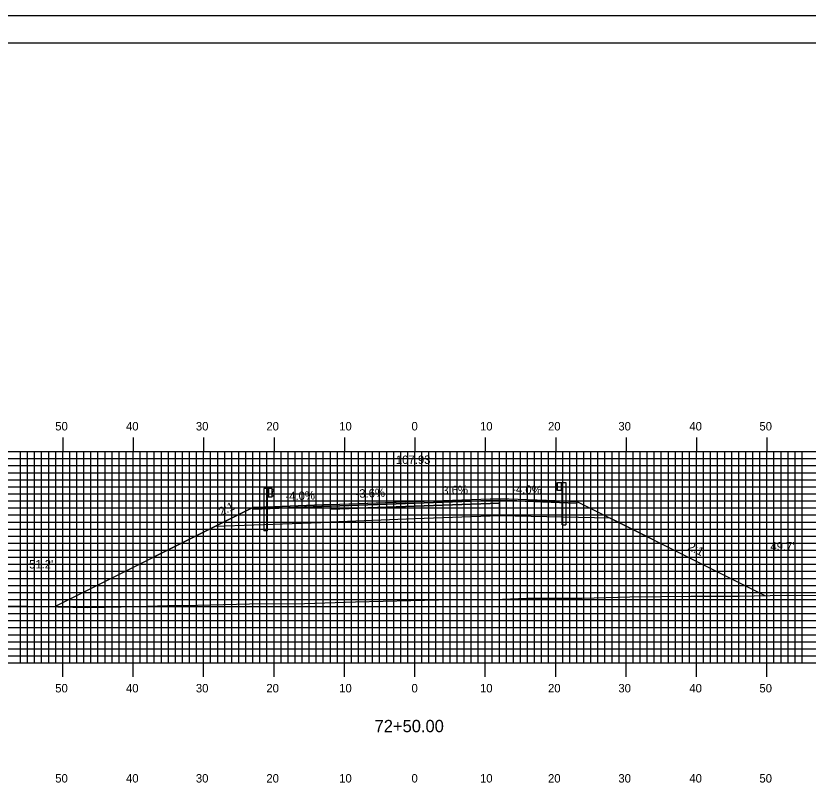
# Model space of a CAD drawing. Extents: x 1760610 to 1760954, y 442591 to 442811.
# Drawn here: x 1760719.5 to 1760832.1, y 442701.2 to 442810.5 of the extents above; entities that cross this region are included whole.
import ezdxf

# ---------------------------------------------------------------- set-up
doc = ezdxf.new("R2010")
doc.units = 0
for name, color, linetype in [('ANNOTATION', 7, 'Continuous'), ('BORDER', 7, 'Continuous'), ('D_Guardrail_Beam_Lt', 7, 'Continuous'), ('D_Guardrail_Beam_Rt', 7, 'Continuous'), ('D_Roadway_Centerline', 7, 'Continuous'), ('D_Roadway_Centerline_Text', 7, 'Continuous'), ('D_Roadway_Edge_Shoulder', 7, 'Continuous'), ('D_Roadway_Edge_TW', 7, 'Continuous'), ('D_Roadway_Pavement', 7, 'Continuous'), ('D_Roadway_SlopeLines', 7, 'Continuous'), ('D_Roadway_SubGrade', 7, 'Continuous'), ('D_Text_Standard', 7, 'Continuous'), ('H_V ANNOTATION', 7, 'Continuous'), ('MAJOR', 7, 'Continuous'), ('MINOR', 7, 'Continuous'), ('PLOT BOUNDARY', 7, 'Continuous'), ('S_Roadway_Centerline', 7, 'Continuous')]:
    doc.layers.add(name, color=color, linetype=linetype)

msp = doc.modelspace()

# ---------------------------------------------------------------- linework, layer by layer
at = {"layer": 'BORDER'}
msp.add_lwpolyline([(1760626.61, 442596.67), (1760946.61, 442596.67), (1760946.61, 442806.67), (1760626.61, 442806.67)], close=True, dxfattribs=at)
at = {"layer": 'D_Guardrail_Beam_Lt'}
for p, q in [((1760754.78, 442743.43), (1760754.78, 442737.43)), ((1760755.26, 442743.43), (1760754.78, 442743.43)), ((1760755.94, 442743.43), (1760755.26, 442743.43)), ((1760755.26, 442743.43), (1760755.26, 442742.26)), ((1760755.32, 442743.43), (1760755.32, 442742.26)), ((1760755.42, 442743.43), (1760755.42, 442742.26)), ((1760755.94, 442742.26), (1760755.94, 442743.43)), ((1760755.94, 442743.34), (1760756.02, 442743.33)), ((1760756.03, 442743.32), (1760756.18, 442743.22)), ((1760755.26, 442742.26), (1760755.94, 442742.26)), ((1760755.28, 442737.43), (1760755.28, 442742.26)), ((1760756.02, 442742.36), (1760755.94, 442742.34)), ((1760755.95, 442742.88), (1760755.95, 442742.81)), ((1760756.18, 442743.08), (1760755.98, 442742.94)), ((1760755.98, 442742.74), (1760756.18, 442742.61)), ((1760756.18, 442742.46), (1760756.03, 442742.36)), ((1760755.28, 442737.43), (1760754.78, 442737.43))]:
    msp.add_line(p, q, dxfattribs=at)
for centre, major_axis, start_param, end_param in [((1760756.01, 442743.29), (0.0417, 0), 0.959931, 1.376053), ((1760756.03, 442742.88), (-0.0789, 0), 5.323254, 6.283185), ((1760756.03, 442742.81), (-0.0789, 0), 6.283185, 7.243116), ((1760756.01, 442742.4), (0.0417, 0), 4.907132, 5.323254), ((1760756.13, 442743.15), (0.0877, 0), 5.323254, 7.243116), ((1760756.13, 442742.54), (0.0877, 0), 5.323254, 7.243116)]:
    msp.add_ellipse(centre, major_axis=major_axis, ratio=0.995501, start_param=start_param, end_param=end_param, dxfattribs=at)
at = {"layer": 'D_Guardrail_Beam_Rt'}
for p, q in [((1760796.39, 442744.19), (1760796.25, 442744.09)), ((1760796.25, 442743.94), (1760796.45, 442743.81)), ((1760796.45, 442743.61), (1760796.25, 442743.47)), ((1760796.25, 442743.33), (1760796.39, 442743.23)), ((1760796.48, 442744.21), (1760796.41, 442744.19)), ((1760796.48, 442744.29), (1760797.17, 442744.29)), ((1760796.48, 442743.12), (1760796.48, 442744.29)), ((1760796.48, 442743.74), (1760796.48, 442743.67)), ((1760797.01, 442744.29), (1760797.01, 442743.12)), ((1760797.11, 442744.29), (1760797.11, 442743.12)), ((1760797.17, 442744.29), (1760797.64, 442744.29)), ((1760797.17, 442744.29), (1760797.17, 442743.12)), ((1760797.64, 442744.29), (1760797.64, 442738.29)), ((1760796.41, 442743.22), (1760796.48, 442743.21)), ((1760797.17, 442743.12), (1760796.48, 442743.12)), ((1760797.15, 442738.29), (1760797.15, 442743.12)), ((1760797.15, 442738.29), (1760797.64, 442738.29))]:
    msp.add_line(p, q, dxfattribs=at)
for centre, major_axis, start_param, end_param in [((1760796.3, 442744.01), (-0.0877, 0), 5.323254, 7.243116), ((1760796.3, 442743.4), (-0.0877, 0), 5.323254, 7.243116), ((1760796.42, 442744.15), (-0.0417, 0), 4.907132, 5.323254), ((1760796.4, 442743.74), (0.0789, 0), 0, 0.959931), ((1760796.4, 442743.67), (0.0789, 0), 5.323254, 6.283185), ((1760796.42, 442743.26), (-0.0417, 0), 0.959931, 1.376053)]:
    msp.add_ellipse(centre, major_axis=major_axis, ratio=0.995501, start_param=start_param, end_param=end_param, dxfattribs=at)
at = {"layer": 'D_Roadway_Centerline'}
msp.add_lwpolyline([(1760725.05, 442726.64), (1760725.08, 442726.65), (1760747.92, 442738.08), (1760751.1, 442739.67), (1760753.21, 442740.72), (1760753.21, 442740.72), (1760754.55, 442740.78), (1760756.21, 442740.84), (1760756.22, 442740.84), (1760764.21, 442741.16), (1760764.22, 442741.16), (1760773.31, 442741.49), (1760776.21, 442741.6), (1760788.21, 442742.03), (1760788.21, 442742.03), (1760796.21, 442741.71), (1760798.09, 442741.63), (1760799.21, 442741.59), (1760799.21, 442741.59), (1760799.22, 442741.59), (1760803.96, 442739.21), (1760803.97, 442739.21), (1760815.77, 442733.31), (1760825.93, 442728.23), (1760825.93, 442728.23)], dxfattribs=at)
at = {"layer": 'D_Roadway_Edge_Shoulder'}
for points in [[(1760764.21, 442741.16), (1760756.21, 442740.84), (1760756.21, 442740.84), (1760753.21, 442740.72), (1760753.21, 442740.47), (1760764.21, 442740.91)], [(1760788.21, 442742.03), (1760796.21, 442741.71), (1760796.21, 442741.71), (1760799.21, 442741.59), (1760799.21, 442741.34), (1760788.21, 442741.78)]]:
    msp.add_lwpolyline(points, close=True, dxfattribs=at)
at = {"layer": 'D_Roadway_Edge_TW'}
for points in [[(1760764.21, 442740.91), (1760764.21, 442741.16), (1760776.21, 442741.6), (1760788.21, 442742.03), (1760788.21, 442741.78), (1760776.21, 442741.35)], [(1760788.21, 442742.03), (1760788.21, 442742.03), (1760788.21, 442741.78), (1760788.21, 442741.78)]]:
    msp.add_lwpolyline(points, close=True, dxfattribs=at)
at = {"layer": 'D_Roadway_Pavement'}
for points in [[(1760764.21, 442740.5), (1760764.21, 442740.91), (1760776.21, 442741.35), (1760788.21, 442741.78), (1760788.21, 442741.36), (1760776.21, 442740.93)], [(1760788.21, 442741.78), (1760788.21, 442741.78), (1760788.21, 442741.36), (1760788.21, 442741.36)]]:
    msp.add_lwpolyline(points, close=True, dxfattribs=at)
for points in [[(1760788.21, 442741.78), (1760788.21, 442741.36)], [(1760788.21, 442741.78), (1760788.21, 442741.36)], [(1760764.21, 442740.91), (1760764.21, 442740.5)]]:
    msp.add_lwpolyline(points, dxfattribs=at)
at = {"layer": 'D_Roadway_SlopeLines'}
for points in [[(1760799.21, 442741.59), (1760825.93, 442728.23)], [(1760753.21, 442740.72), (1760725.05, 442726.64)]]:
    msp.add_lwpolyline(points, dxfattribs=at)
at = {"layer": 'D_Roadway_SubGrade'}
for points in [[(1760764.21, 442738.66), (1760764.21, 442740.5), (1760776.21, 442740.93), (1760788.21, 442741.36), (1760788.21, 442739.53), (1760776.21, 442739.1)], [(1760788.21, 442741.36), (1760788.21, 442741.78), (1760799.21, 442741.34), (1760799.21, 442741.59), (1760803.96, 442739.21), (1760788.21, 442739.53)], [(1760788.21, 442741.36), (1760788.21, 442741.36), (1760788.21, 442739.53), (1760788.21, 442739.53)], [(1760764.21, 442740.5), (1760764.21, 442740.91), (1760753.21, 442740.47), (1760753.21, 442740.72), (1760747.92, 442738.08), (1760764.21, 442738.66)]]:
    msp.add_lwpolyline(points, close=True, dxfattribs=at)
at = {"layer": 'MAJOR'}
for p, q in [((1760726.21, 442750.67), (1760726.21, 442748.67)), ((1760736.21, 442750.67), (1760736.21, 442748.67)), ((1760746.21, 442750.67), (1760746.21, 442748.67)), ((1760756.21, 442750.67), (1760756.21, 442748.67)), ((1760766.21, 442750.67), (1760766.21, 442748.67)), ((1760776.21, 442750.67), (1760776.21, 442748.67)), ((1760786.21, 442750.67), (1760786.21, 442748.67)), ((1760796.21, 442750.67), (1760796.21, 442748.67)), ((1760806.21, 442750.67), (1760806.21, 442748.67)), ((1760816.21, 442750.67), (1760816.21, 442748.67)), ((1760826.21, 442750.67), (1760826.21, 442748.67)), ((1760636.21, 442748.67), (1760916.21, 442748.67)), ((1760636.21, 442748.67), (1760916.21, 442748.67)), ((1760726.21, 442718.67), (1760726.21, 442748.67)), ((1760736.21, 442718.67), (1760736.21, 442748.67)), ((1760746.21, 442718.67), (1760746.21, 442748.67)), ((1760756.21, 442718.67), (1760756.21, 442748.67)), ((1760766.21, 442718.67), (1760766.21, 442748.67)), ((1760776.21, 442718.67), (1760776.21, 442748.67)), ((1760786.21, 442718.67), (1760786.21, 442748.67)), ((1760796.21, 442718.67), (1760796.21, 442748.67)), ((1760806.21, 442718.67), (1760806.21, 442748.67)), ((1760816.21, 442718.67), (1760816.21, 442748.67)), ((1760826.21, 442718.67), (1760826.21, 442748.67)), ((1760636.21, 442743.67), (1760916.21, 442743.67)), ((1760636.21, 442738.67), (1760916.21, 442738.67)), ((1760636.21, 442733.67), (1760916.21, 442733.67)), ((1760636.21, 442728.67), (1760916.21, 442728.67)), ((1760636.21, 442723.67), (1760916.21, 442723.67)), ((1760636.21, 442718.67), (1760916.21, 442718.67)), ((1760636.21, 442718.67), (1760916.21, 442718.67)), ((1760726.21, 442716.66), (1760726.21, 442718.67)), ((1760736.21, 442716.66), (1760736.21, 442718.67)), ((1760746.21, 442716.66), (1760746.21, 442718.67)), ((1760756.21, 442716.66), (1760756.21, 442718.67)), ((1760766.21, 442716.66), (1760766.21, 442718.67)), ((1760776.21, 442716.66), (1760776.21, 442718.67)), ((1760786.21, 442716.66), (1760786.21, 442718.67)), ((1760796.21, 442716.66), (1760796.21, 442718.67)), ((1760806.21, 442716.66), (1760806.21, 442718.67)), ((1760816.21, 442716.66), (1760816.21, 442718.67)), ((1760826.21, 442716.66), (1760826.21, 442718.67))]:
    msp.add_line(p, q, dxfattribs=at)
at = {"layer": 'MINOR'}
for p, q in [((1760720.21, 442718.67), (1760720.21, 442748.67)), ((1760721.21, 442718.67), (1760721.21, 442748.67)), ((1760722.21, 442718.67), (1760722.21, 442748.67)), ((1760723.21, 442718.67), (1760723.21, 442748.67)), ((1760724.21, 442718.67), (1760724.21, 442748.67)), ((1760725.21, 442718.67), (1760725.21, 442748.67)), ((1760727.21, 442718.67), (1760727.21, 442748.67)), ((1760728.21, 442718.67), (1760728.21, 442748.67)), ((1760729.21, 442718.67), (1760729.21, 442748.67)), ((1760730.21, 442718.67), (1760730.21, 442748.67)), ((1760731.21, 442718.67), (1760731.21, 442748.67)), ((1760732.21, 442718.67), (1760732.21, 442748.67)), ((1760733.21, 442718.67), (1760733.21, 442748.67)), ((1760734.21, 442718.67), (1760734.21, 442748.67)), ((1760735.21, 442718.67), (1760735.21, 442748.67)), ((1760737.21, 442718.67), (1760737.21, 442748.67)), ((1760738.21, 442718.67), (1760738.21, 442748.67)), ((1760739.21, 442718.67), (1760739.21, 442748.67)), ((1760740.21, 442718.67), (1760740.21, 442748.67)), ((1760741.21, 442718.67), (1760741.21, 442748.67)), ((1760742.21, 442718.67), (1760742.21, 442748.67)), ((1760743.21, 442718.67), (1760743.21, 442748.67)), ((1760744.21, 442718.67), (1760744.21, 442748.67)), ((1760745.21, 442718.67), (1760745.21, 442748.67)), ((1760747.21, 442718.67), (1760747.21, 442748.67)), ((1760748.21, 442718.67), (1760748.21, 442748.67)), ((1760749.21, 442718.67), (1760749.21, 442748.67)), ((1760750.21, 442718.67), (1760750.21, 442748.67)), ((1760751.21, 442718.67), (1760751.21, 442748.67)), ((1760752.21, 442718.67), (1760752.21, 442748.67)), ((1760753.21, 442718.67), (1760753.21, 442748.67)), ((1760754.21, 442718.67), (1760754.21, 442748.67)), ((1760755.21, 442718.67), (1760755.21, 442748.67)), ((1760757.21, 442718.67), (1760757.21, 442748.67)), ((1760758.21, 442718.67), (1760758.21, 442748.67)), ((1760759.21, 442718.67), (1760759.21, 442748.67)), ((1760760.21, 442718.67), (1760760.21, 442748.67)), ((1760761.21, 442718.67), (1760761.21, 442748.67)), ((1760762.21, 442718.67), (1760762.21, 442748.67)), ((1760763.21, 442718.67), (1760763.21, 442748.67)), ((1760764.21, 442718.67), (1760764.21, 442748.67)), ((1760765.21, 442718.67), (1760765.21, 442748.67)), ((1760767.21, 442718.67), (1760767.21, 442748.67)), ((1760768.21, 442718.67), (1760768.21, 442748.67)), ((1760769.21, 442718.67), (1760769.21, 442748.67)), ((1760770.21, 442718.67), (1760770.21, 442748.67)), ((1760771.21, 442718.67), (1760771.21, 442748.67)), ((1760772.21, 442718.67), (1760772.21, 442748.67)), ((1760773.21, 442718.67), (1760773.21, 442748.67)), ((1760774.21, 442718.67), (1760774.21, 442748.67)), ((1760775.21, 442718.67), (1760775.21, 442748.67)), ((1760777.21, 442718.67), (1760777.21, 442748.67)), ((1760778.21, 442718.67), (1760778.21, 442748.67)), ((1760779.21, 442718.67), (1760779.21, 442748.67)), ((1760780.21, 442718.67), (1760780.21, 442748.67)), ((1760781.21, 442718.67), (1760781.21, 442748.67)), ((1760782.21, 442718.67), (1760782.21, 442748.67)), ((1760783.21, 442718.67), (1760783.21, 442748.67)), ((1760784.21, 442718.67), (1760784.21, 442748.67)), ((1760785.21, 442718.67), (1760785.21, 442748.67)), ((1760787.21, 442718.67), (1760787.21, 442748.67)), ((1760788.21, 442718.67), (1760788.21, 442748.67)), ((1760789.21, 442718.67), (1760789.21, 442748.67)), ((1760790.21, 442718.67), (1760790.21, 442748.67)), ((1760791.21, 442718.67), (1760791.21, 442748.67)), ((1760792.21, 442718.67), (1760792.21, 442748.67)), ((1760793.21, 442718.67), (1760793.21, 442748.67)), ((1760794.21, 442718.67), (1760794.21, 442748.67)), ((1760795.21, 442718.67), (1760795.21, 442748.67)), ((1760797.21, 442718.67), (1760797.21, 442748.67)), ((1760798.21, 442718.67), (1760798.21, 442748.67)), ((1760799.21, 442718.67), (1760799.21, 442748.67)), ((1760800.21, 442718.67), (1760800.21, 442748.67)), ((1760801.21, 442718.67), (1760801.21, 442748.67)), ((1760802.21, 442718.67), (1760802.21, 442748.67)), ((1760803.21, 442718.67), (1760803.21, 442748.67)), ((1760804.21, 442718.67), (1760804.21, 442748.67)), ((1760805.21, 442718.67), (1760805.21, 442748.67)), ((1760807.21, 442718.67), (1760807.21, 442748.67)), ((1760808.21, 442718.67), (1760808.21, 442748.67)), ((1760809.21, 442718.67), (1760809.21, 442748.67)), ((1760810.21, 442718.67), (1760810.21, 442748.67)), ((1760811.21, 442718.67), (1760811.21, 442748.67)), ((1760812.21, 442718.67), (1760812.21, 442748.67)), ((1760813.21, 442718.67), (1760813.21, 442748.67)), ((1760814.21, 442718.67), (1760814.21, 442748.67)), ((1760815.21, 442718.67), (1760815.21, 442748.67)), ((1760817.21, 442718.67), (1760817.21, 442748.67)), ((1760818.21, 442718.67), (1760818.21, 442748.67)), ((1760819.21, 442718.67), (1760819.21, 442748.67)), ((1760820.21, 442718.67), (1760820.21, 442748.67)), ((1760821.21, 442718.67), (1760821.21, 442748.67)), ((1760822.21, 442718.67), (1760822.21, 442748.67)), ((1760823.21, 442718.67), (1760823.21, 442748.67)), ((1760824.21, 442718.67), (1760824.21, 442748.67)), ((1760825.21, 442718.67), (1760825.21, 442748.67)), ((1760827.21, 442718.67), (1760827.21, 442748.67)), ((1760828.21, 442718.67), (1760828.21, 442748.67)), ((1760829.21, 442718.67), (1760829.21, 442748.67)), ((1760830.21, 442718.67), (1760830.21, 442748.67)), ((1760831.21, 442718.67), (1760831.21, 442748.67)), ((1760636.21, 442747.67), (1760916.21, 442747.67)), ((1760636.21, 442746.67), (1760916.21, 442746.67)), ((1760636.21, 442745.67), (1760916.21, 442745.67)), ((1760636.21, 442744.67), (1760916.21, 442744.67)), ((1760636.21, 442742.67), (1760916.21, 442742.67)), ((1760636.21, 442741.67), (1760916.21, 442741.67)), ((1760636.21, 442740.67), (1760916.21, 442740.67)), ((1760636.21, 442739.67), (1760916.21, 442739.67)), ((1760636.21, 442737.67), (1760916.21, 442737.67)), ((1760636.21, 442736.67), (1760916.21, 442736.67)), ((1760636.21, 442735.67), (1760916.21, 442735.67)), ((1760636.21, 442734.67), (1760916.21, 442734.67)), ((1760636.21, 442732.67), (1760916.21, 442732.67)), ((1760636.21, 442731.67), (1760916.21, 442731.67)), ((1760636.21, 442730.67), (1760916.21, 442730.67)), ((1760636.21, 442729.67), (1760916.21, 442729.67)), ((1760636.21, 442727.67), (1760916.21, 442727.67)), ((1760636.21, 442726.67), (1760916.21, 442726.67)), ((1760636.21, 442725.67), (1760916.21, 442725.67)), ((1760636.21, 442724.67), (1760916.21, 442724.67)), ((1760636.21, 442722.67), (1760916.21, 442722.67)), ((1760636.21, 442721.67), (1760916.21, 442721.67)), ((1760636.21, 442720.67), (1760916.21, 442720.67)), ((1760636.21, 442719.67), (1760916.21, 442719.67))]:
    msp.add_line(p, q, dxfattribs=at)
at = {"layer": 'PLOT BOUNDARY'}
msp.add_lwpolyline([(1760610.43, 442590.55), (1760950.43, 442590.55), (1760950.43, 442810.55), (1760610.43, 442810.55)], close=True, dxfattribs=at)
at = {"layer": 'S_Roadway_Centerline'}
msp.add_lwpolyline([(1760714.94, 442726.8), (1760721.21, 442726.74), (1760729.78, 442726.53), (1760736.85, 442726.65), (1760741.08, 442726.83), (1760745.33, 442726.85), (1760752.72, 442727.06), (1760760.55, 442727.11), (1760767.79, 442727.31), (1760783.51, 442727.72), (1760787.51, 442727.65), (1760792.06, 442727.84), (1760799.99, 442727.87), (1760806.75, 442728.06), (1760815.38, 442728.16), (1760822.07, 442728.16), (1760828.99, 442728.28), (1760833.91, 442728.23)], dxfattribs=at)

# ---------------------------------------------------------------- texts
at = {"layer": 'ANNOTATION'}
for s, rotation, p in [('-3.6%', 2.0618, (1760767.8, 442742.09)), ('3.6%', 2.0618, (1760780.12, 442742.54)), ('-4.0%', 357.7093, (1760790.01, 442742.76)), ('-4.0%', 2.2907, (1760757.85, 442741.71)), ('2:1', 26.5699, (1760748.71, 442739.51)), ('2:1', 333.4347, (1760814.88, 442734.79))]:
    msp.add_text(s, height=1.2, rotation=rotation, dxfattribs=at).set_placement(p)
at = {"layer": 'D_Roadway_Centerline'}
for s, p in [('C', (1760776.21, 442741.6)), ('L', (1760776.21, 442741.59))]:
    msp.add_text(s, height=0.0146, dxfattribs=at).set_placement(p)
at = {"layer": 'D_Roadway_Centerline_Text'}
msp.add_text('107.93', height=1.2, dxfattribs=at).set_placement((1760773.52, 442746.91))
at = {"layer": 'D_Text_Standard'}
for s, p in [("49.7'", (1760826.7, 442734.62)), ("51.2'", (1760721.42, 442732.07))]:
    msp.add_text(s, height=1.2, dxfattribs=at).set_placement(p)
at = {"layer": 'H_V ANNOTATION'}
for s, height, p in [('50', 1.2, (1760725.14, 442751.67)), ('40', 1.2, (1760735.19, 442751.67)), ('30', 1.2, (1760745.11, 442751.67)), ('20', 1.2, (1760755.12, 442751.67)), ('10', 1.2, (1760765.46, 442751.67)), ('0', 1.2, (1760775.73, 442751.67)), ('10', 1.2, (1760785.46, 442751.67)), ('20', 1.2, (1760795.12, 442751.67)), ('30', 1.2, (1760805.11, 442751.67)), ('40', 1.2, (1760815.19, 442751.67)), ('50', 1.2, (1760825.14, 442751.67)), ('50', 1.2, (1760725.14, 442714.47)), ('40', 1.2, (1760735.19, 442714.47)), ('30', 1.2, (1760745.11, 442714.47)), ('20', 1.2, (1760755.12, 442714.47)), ('10', 1.2, (1760765.46, 442714.47)), ('0', 1.2, (1760775.73, 442714.47)), ('10', 1.2, (1760785.46, 442714.47)), ('20', 1.2, (1760795.12, 442714.47)), ('30', 1.2, (1760805.11, 442714.47)), ('40', 1.2, (1760815.19, 442714.47)), ('50', 1.2, (1760825.14, 442714.47)), ('72+50.00', 1.75, (1760770.5, 442708.82)), ('50', 1.2, (1760725.14, 442701.67)), ('40', 1.2, (1760735.19, 442701.67)), ('30', 1.2, (1760745.11, 442701.67)), ('20', 1.2, (1760755.12, 442701.67)), ('10', 1.2, (1760765.46, 442701.67)), ('0', 1.2, (1760775.73, 442701.67)), ('10', 1.2, (1760785.46, 442701.67)), ('20', 1.2, (1760795.12, 442701.67)), ('30', 1.2, (1760805.11, 442701.67)), ('40', 1.2, (1760815.19, 442701.67)), ('50', 1.2, (1760825.14, 442701.67))]:
    msp.add_text(s, height=height, dxfattribs=at).set_placement(p)

doc.saveas('drawing.dxf')
